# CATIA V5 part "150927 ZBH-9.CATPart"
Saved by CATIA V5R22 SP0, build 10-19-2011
Part number: 150927 ZBH-9
Property "ParasolidId": 24
Property "PSOL_INSTNR": 8
Property "ParasolidId": 21
Property "PSOL_INSTNR": 8
Property "ParasolidId": 12
Property "PSOL_INSTNR": 8
Property "ParasolidId": 9
Property "PSOL_INSTNR": 8
Bounding box of the stored display mesh (mm): x 0 to 4, y -4.5 to 4.5, z -4.5 to 4.5
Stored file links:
  U:\S9A\PER\CAO\Assemblage\Cadre\Chariot_Y\Prehenseur\150927 ZBH-9.CATPart
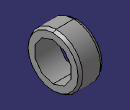
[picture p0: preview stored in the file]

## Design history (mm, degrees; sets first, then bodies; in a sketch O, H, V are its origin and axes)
Body1 "150927 ZBH-9" (main body)
  Solid1: solid without history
